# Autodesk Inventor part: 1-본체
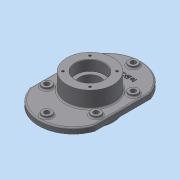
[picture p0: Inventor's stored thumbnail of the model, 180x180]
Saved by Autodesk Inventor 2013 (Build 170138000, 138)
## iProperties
Created: 2015-02
Part Number: 1-본체
Material: 일반
Document SubType Name: Modeling
Designer: dgall
Density: 1 g/cm^3
Author: dgall
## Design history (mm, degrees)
sketch "스케치1"
  geometry: L1 (-70, 60)-(70, 60); L2 (70, 60)-(70, -60); L3 (70, -60)-(-70, -60); L4 (-70, -60)-(-70, 60); A1 r 74 centre (0, 36) between (70, 60) and (-70, 60); A2 r 74 centre (0, -36) between (-70, -60) and (70, -60); 3 further points
  constraints: 8 end point, 4 point on circle, 2 centre point, 2 midpoint, 2 parallel, 1 equal radius, 1 horizontal, 1 horizontal alignment, 1 perpendicular, 1 vertical alignment
  dimensions: "d0" = 120 distance of L3.end L1.start; "d3" = 140 distance between parallel lines of L2 L4; "d4" = 74 radius of A1
extrude "돌출1" new body sketch "스케치1" distance "d6" = 12; taper "d7" = 0 deg
sketch "스케치2"
  geometry: C1 r 50 at (0, 0); 1 further point
  constraints: 1 centre point, 1 coincident
  dimensions: "d8" = 100 diameter of C1
extrude "돌출2" join sketch "스케치2" distance "d10" = 23; taper "d11" = 0 deg
sketch "스케치3"
  geometry: C1 r 50 at (0, 0) reference; C2 r 31 at (0, 0)
  constraints: 1 centre point, 1 coincident
  dimensions: "d12" = 62 diameter of C2
extrude "돌출3" cut sketch "스케치3" distance "d14" = 22; taper "d15" = 0 deg
sketch "스케치4"
  geometry: C1 r 50 at (0, 0); 1 further point
  constraints: 1 centre point, 1 coincident
  dimensions: "d16" = 100 diameter of C1
extrude "돌출4" join sketch "스케치4" distance "d18" = 35; taper "d19" = 0 deg
sketch "스케치5"
  geometry: C1 r 50 at (0, 0) reference; C2 r 31 at (0, 0)
  constraints: 1 centre point, 1 coincident
  dimensions: "d20" = 62 diameter of C2
extrude "돌출5" cut sketch "스케치5" distance "d22" = 22; taper "d23" = 0 deg
sketch "스케치6"
  geometry: C1 r 50 at (0, 0) reference; C2 r 22.5 at (0, 0)
  constraints: 1 centre point, 1 coincident
  dimensions: "d24" = 45 diameter of C2
extrude "돌출6" cut sketch "스케치6" stored distance "d26" = 22; taper "d27" = 0 deg
chamfer "모따기1" distance "d28" = 1; stored, may be unused: second distance "d29" = 2, angle "d30" = 45 deg
fillet "모깎기1" dims "d31" = 0.3
sketch "스케치7"
  geometry: L1 (0, 0)-(-41, 0); L2 (0, 0)-(-53.009, 53.009); C1 r 32 at (0, 0) reference; C2 r 3 at (-28.991, 28.991); A1 r 41 centre (0, 0) between (-41, 0) and (-28.991, 28.991)
  constraints: 4 end point, 2 centre point, 2 point on circle, 1 coincident, 1 horizontal, 1 point on line
  dimensions: "d33" = 82 diameter of A1; "d36" = 45 deg angle of L2 L1; "d38" = 6 diameter of C2
hole "구멍1" sketch "스케치7" at (-28.991, 28.991) diameter "d39" = 4.917; stored, may be unused: countersink angle "d43" = 90 deg, drill point angle "d45" = 118 deg; dims "d40" = 10, "d41" = 4, "d42" = 2, "d44" = 13
fillet "모깎기3" dims "d49" = 3
node "작업 평면2"
sketch "스케치8"
  geometry: L1 (-70, 60)-(-70, -60) reference; L2 (70, -60)-(70, 60) reference; L3 (-53, -56.976)-(-53, 56.976); L4 (53, 56.976)-(53, -56.976); C1 r 10 at (0, -93); C2 r 10 at (0, 93); C3 r 10 at (53, -39.976); C4 r 10 at (53, 39.976); C5 r 10 at (-53, 39.976); C6 r 10 at (-53, -39.976); A1 r 74 centre (0, -36) between (-70, -60) and (70, -60) reference; A2 r 74 centre (0, 36) between (70, 60) and (-70, 60) reference; A3 r 57 centre (0, 36) between (53, 56.976) and (-53, 56.976); A4 r 57 centre (0, -36) between (-53, -56.976) and (53, -56.976)
  constraints: 8 centre point, 6 point on circle, 4 end point, 4 point on line, 3 equal radius, 1 vertical alignment, 3 other
  dimensions: "d50" = 17 distance between parallel lines of L1 L3; "d51" = 20 diameter of C1; "d52" = 20 diameter of C2; "d54" = 20 diameter of C3; "d55" = 17 distance of L4.end C3.centre; "d56" = 17 distance of L4.start C4.centre; "d57" = 17 distance of L3.end C5.centre; "d58" = 17 distance of L3.start C6.centre
extrude "돌출7" join sketch "스케치8" distance "d59" = 5; taper "d60" = 0 deg
fillet "모깎기4" dims "d61" = 3
fillet "모깎기5" dims "d62" = 3
sketch "스케치9"
  geometry: C1 r 10 at (0, 0) reference; C2 r 5.5 at (0, 0); 1 further point
  constraints: 1 centre point, 1 coincident
  dimensions: "d63" = 11 diameter of C2
extrude "돌출8" cut sketch "스케치9" stored distance "d65" = 5; taper "d66" = 0 deg
sketch "스케치10"
  geometry: C1 r 10 at (0, 0) reference; C2 r 5.5 at (0, 0); 1 further point
  constraints: 1 centre point, 1 coincident
  dimensions: "d67" = 11 diameter of C2
extrude "돌출9" cut sketch "스케치10" stored distance "d69" = 5; taper "d70" = 0 deg
sketch "스케치11"
  geometry: C1 r 10 at (0, 0) reference; C2 r 5.5 at (0, 0); C3 r 10 at (106, 0) reference; C4 r 5.5 at (106, 0); 1 further point
  constraints: 2 centre point, 2 coincident, 1 equal radius
  dimensions: "d77" = 11 diameter of C2
extrude "돌출10" cut sketch "스케치11" stored distance "d79" = 5; taper "d80" = 0 deg
sketch "스케치12"
  geometry: C1 r 53 at (0, 0) reference; A1 r 71 centre (0, 36) between (67, 59.495) and (-67, 59.495) reference; 1 further point
  constraints: 1 vertical alignment, 1 other
  dimensions: "d81" = 65 distance of C1.centre point (0, 65)
feature "엠보싱1" sketch "스케치12" dims "d0" = 120, "d3" = 140, "d4" = 74, "d82" = 1, "d83" = 0
node "솔리드1"
pattern_circular "원형 패턴1" dims angle "d47" = 360 deg
mirror "대칭1"
pattern_circular "원형 패턴2" dims angle "d72" = 360 deg
pattern_linear "직사각형 패턴1" dims "d76" = 106
